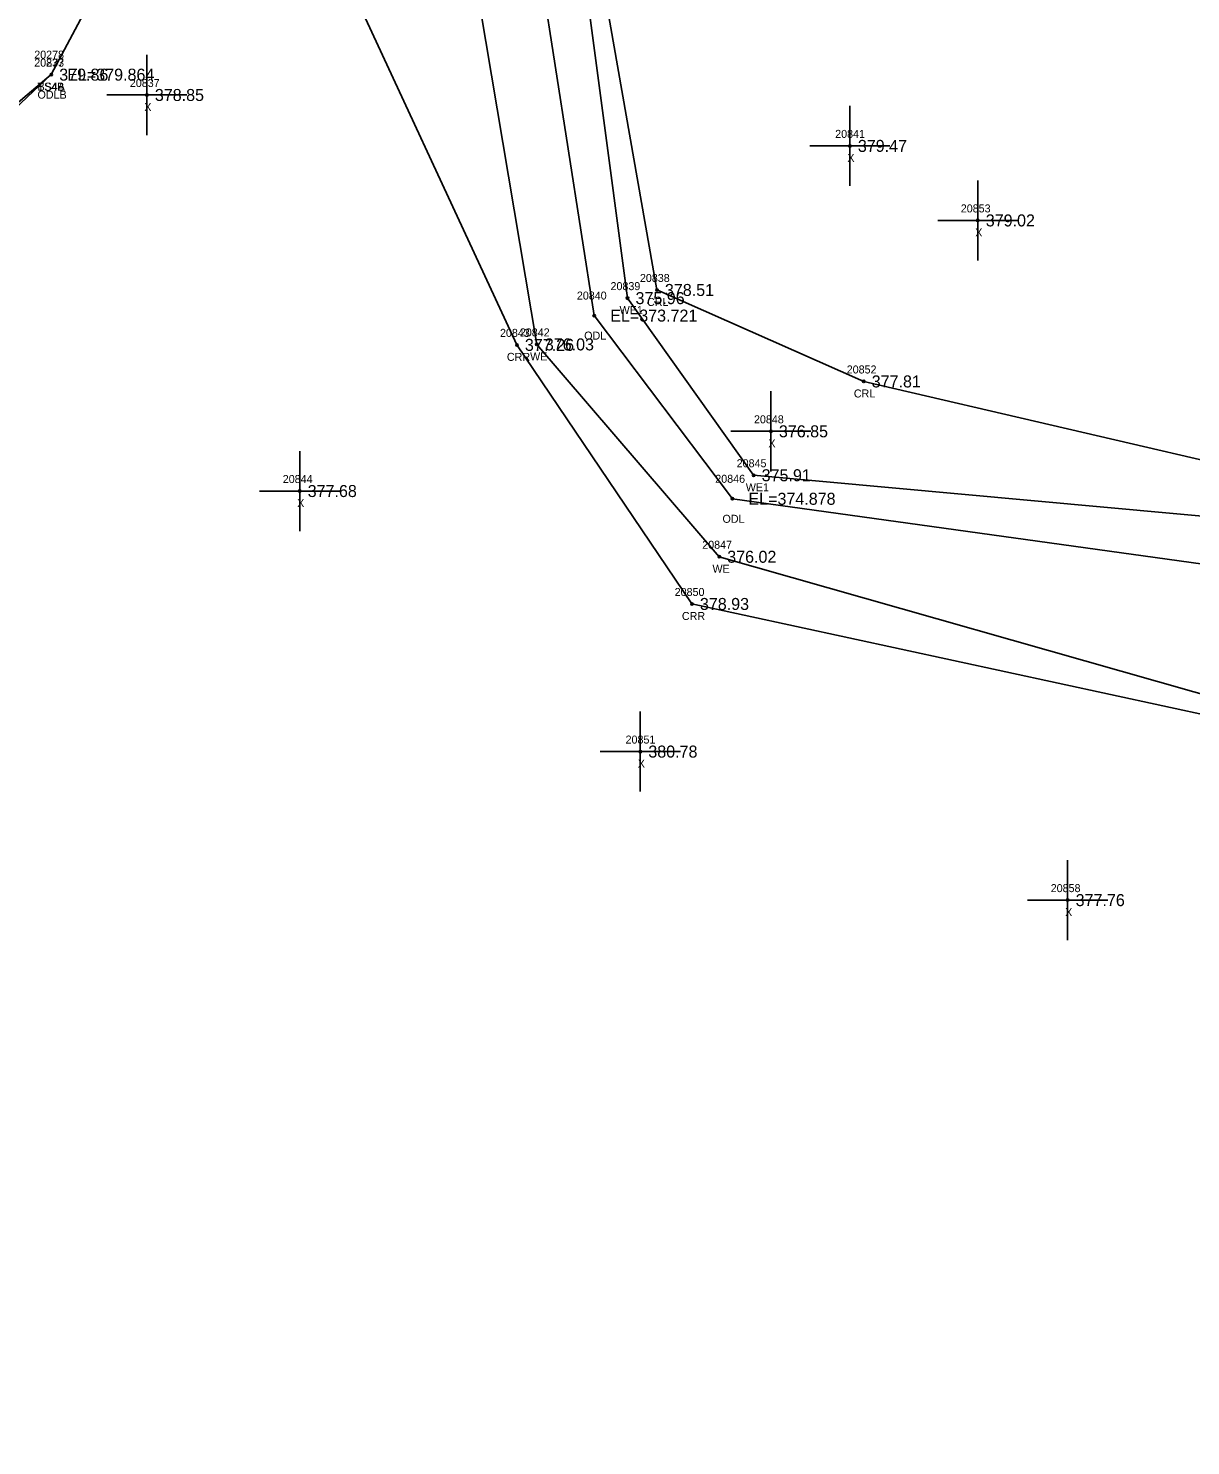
# Model space of a CAD drawing. Extents: x 2116373 to 2118139, y 979529 to 981026.
# Drawn here: x 2117341.9 to 2117487.1, y 979924.3 to 980101.3 of the extents above; entities that cross this region are included whole.
import ezdxf

# ---------------------------------------------------------------- set-up
doc = ezdxf.new("R2010")
doc.units = 0
for name, color, linetype in [('RD_DTM_BkLn2', 7, 'Continuous'), ('RD_DTM_BkLn_txCode', 7, 'Continuous'), ('RD_EX_H2O', 7, 'Continuous'), ('RD_EX_H2O_txCode', 7, 'Continuous'), ('RD_EX_Misc', 7, 'Continuous'), ('RD_EX_Misc_txCode', 7, 'Continuous'), ('RD_EX_TX_H2O_ELEV', 7, 'Continuous'), ('RD_EX_TX_Misc_ELEV', 7, 'Continuous'), ('RD_SMD_Locator', 7, 'Continuous')]:
    doc.layers.add(name, color=color, linetype=linetype)

msp = doc.modelspace()

# ---------------------------------------------------------------- linework, layer by layer
at = {"layer": 'RD_DTM_BkLn2'}
for points in [[(2117344.8, 980095.54), (2117358.39, 980121.14), (2117356.54, 980132.72)], [(2116934.42, 979772.82), (2116956.11, 979780.15), (2116996.15, 979805.42), (2117040.3, 979838.56), (2117080.53, 979868.79), (2117120.95, 979906.28), (2117189.36, 979974.74), (2117275.31, 980029.9), (2117344.8, 980095.54)]]:
    msp.add_lwpolyline(points, dxfattribs=at)
at = {"layer": 'RD_EX_H2O'}
for points in [[(2117055.27, 980533.4), (2117084.87, 980468.5), (2117113.12, 980396.82), (2117150.26, 980360.48), (2117172.14, 980330.53), (2117167.4, 980300.56), (2117152, 980282.05), (2117153.33, 980268.31), (2117164.01, 980260.72), (2117221.6, 980247.26), (2117265.25, 980211.02), (2117324.27, 980199.15), (2117347.37, 980175.31), (2117365.85, 980182.55), (2117389.45, 980162.29), (2117399.63, 980142.01), (2117411.26, 980120.88), (2117420.42, 980068.64), (2117446.24, 980057.21), (2117497.11, 980045.39), (2117594.71, 979999.33), (2117646.33, 979985.56), (2117750.91, 980032.44), (2117805.09, 980018.87)], [(2117320.83, 980195.76), (2117348.44, 980166.4), (2117344.42, 980159.47), (2117364.05, 980141.59), (2117409.75, 980120.17), (2117416.75, 980067.62), (2117432.5, 980045.49), (2117502.17, 980039.14), (2117583.98, 979987.26), (2117646.81, 979981.12), (2117705, 980001.51), (2117745.64, 980024.24), (2117805.06, 980014.37)], [(2117253.76, 980181.57), (2117309.73, 980180.01), (2117328.75, 980169.13), (2117302.89, 980172.19), (2117303.47, 980157.54), (2117331.87, 980146.51), (2117356.54, 980132.72), (2117379.52, 980112.38), (2117402.94, 980061.78), (2117424.79, 980029.41), (2117490.12, 980015.27), (2117551.05, 979984.61)], [(2117327.56, 980176.76), (2117343.89, 980156.23), (2117361.71, 980140.22), (2117404.48, 980117.53), (2117412.59, 980065.44), (2117429.85, 980042.55), (2117500.31, 980032.76), (2117583.13, 979982.49), (2117644.33, 979974.23), (2117711.62, 979990.62), (2117746.36, 980006.72), (2117805.28, 980007.14)], [(2117334.27, 980149.08), (2117359.88, 980134.92), (2117396.25, 980116.57), (2117405.43, 980061.84), (2117428.2, 980035.31), (2117491.98, 980017.16), (2117553.53, 979985.3), (2117578.12, 979975.29), (2117646.29, 979963.95), (2117711.26, 979981.91), (2117748.87, 979990.36), (2117810.8, 979988.9)], [(2116934.42, 979772.82), (2116952.72, 979786.01), (2116992.31, 979812.05), (2117036.21, 979845.2), (2117073.01, 979877), (2117113.79, 979913.05), (2117185.72, 979978.24), (2117270.2, 980032.33), (2117344.8, 980095.54)]]:
    msp.add_lwpolyline(points, dxfattribs=at)
at = {"layer": 'RD_EX_Misc'}
for p, q in [((2117356.74, 980088), (2117356.74, 980098)), ((2117351.74, 980093), (2117361.74, 980093)), ((2117444.51, 980081.64), (2117444.51, 980091.64)), ((2117439.51, 980086.64), (2117449.51, 980086.64)), ((2117460.48, 980072.33), (2117460.48, 980082.33)), ((2117455.48, 980077.33), (2117465.48, 980077.33)), ((2117434.65, 980045.98), (2117434.65, 980055.98)), ((2117429.65, 980050.98), (2117439.65, 980050.98)), ((2117375.82, 980038.52), (2117375.82, 980048.52)), ((2117370.82, 980043.52), (2117380.82, 980043.52)), ((2117418.35, 980005.97), (2117418.35, 980015.97)), ((2117413.35, 980010.97), (2117423.35, 980010.97)), ((2117471.7, 979987.41), (2117471.7, 979997.41)), ((2117466.7, 979992.41), (2117476.7, 979992.41))]:
    msp.add_line(p, q, dxfattribs=at)
at = {"layer": 'RD_SMD_Locator'}
for centre in [(2117344.8, 980095.54), (2117344.8, 980095.54), (2117344.8, 980095.54), (2117356.74, 980093), (2117444.51, 980086.64), (2117460.48, 980077.33), (2117420.42, 980068.64), (2117416.75, 980067.62), (2117412.59, 980065.44), (2117402.94, 980061.78), (2117405.43, 980061.84), (2117446.24, 980057.21), (2117434.65, 980050.98), (2117432.5, 980045.49), (2117375.82, 980043.52), (2117429.85, 980042.55), (2117428.2, 980035.31), (2117424.79, 980029.41), (2117418.35, 980010.97), (2117471.7, 979992.41)]:
    msp.add_circle(centre, 0.15, dxfattribs=at)

# ---------------------------------------------------------------- texts
at = {"layer": 'RD_DTM_BkLn_txCode'}
for s, p in [('20277', (2117342.68, 980096.54)), ('20833', (2117342.68, 980096.54)), ('TS4B', (2117343.09, 980093.54)), ('BS4A', (2117343.09, 980093.54))]:
    msp.add_text(s, height=1, dxfattribs=at).set_placement(p)
at = {"layer": 'RD_EX_H2O_txCode'}
for s, p in [('20278', (2117342.68, 980097.54)), ('ODLB', (2117343.09, 980092.54)), ('20838', (2117418.3, 980069.64)), ('20839', (2117414.63, 980068.62)), ('20840', (2117410.43, 980067.44)), ('CRL', (2117419.19, 980066.64)), ('WE1', (2117415.76, 980065.62)), ('20843', (2117400.83, 980062.78)), ('20842', (2117403.31, 980062.84)), ('ODL', (2117411.34, 980062.44)), ('CRR', (2117401.69, 980059.78)), ('WE', (2117404.59, 980059.84)), ('20852', (2117444.12, 980058.21)), ('CRL', (2117445.01, 980055.21)), ('20845', (2117430.38, 980046.49)), ('20846', (2117427.71, 980044.55)), ('WE1', (2117431.52, 980043.49)), ('ODL', (2117428.61, 980039.55)), ('20847', (2117426.08, 980036.31)), ('WE', (2117427.36, 980033.31)), ('20850', (2117422.64, 980030.41)), ('CRR', (2117423.54, 980027.41))]:
    msp.add_text(s, height=1, dxfattribs=at).set_placement(p)
at = {"layer": 'RD_EX_Misc_txCode'}
for s, p in [('20837', (2117354.62, 980094)), ('X', (2117356.42, 980091)), ('20841', (2117442.68, 980087.64)), ('X', (2117444.2, 980084.64)), ('20853', (2117458.36, 980078.33)), ('X', (2117460.16, 980075.33)), ('20848', (2117432.54, 980051.98)), ('X', (2117434.34, 980048.98)), ('20844', (2117373.71, 980044.52)), ('X', (2117375.51, 980041.52)), ('20851', (2117416.51, 980011.97)), ('X', (2117418.03, 980008.97)), ('20858', (2117469.59, 979993.41)), ('X', (2117471.39, 979990.41))]:
    msp.add_text(s, height=1, dxfattribs=at).set_placement(p)
at = {"layer": 'RD_EX_TX_H2O_ELEV'}
for s, p in [('EL=379.864', (2117346.8, 980094.79)), ('378.51', (2117421.42, 980067.89)), ('375.96', (2117417.75, 980066.87)), ('EL=373.721', (2117414.59, 980064.69)), ('377.26', (2117403.94, 980061.03)), ('376.03', (2117406.43, 980061.09)), ('377.81', (2117447.24, 980056.46)), ('375.91', (2117433.5, 980044.74)), ('EL=374.878', (2117431.85, 980041.8)), ('376.02', (2117429.2, 980034.56)), ('378.93', (2117425.79, 980028.66))]:
    msp.add_text(s, height=1.5, dxfattribs=at).set_placement(p)
at = {"layer": 'RD_EX_TX_Misc_ELEV'}
for s, p in [('379.86', (2117345.8, 980094.79)), ('379.86', (2117345.8, 980094.79)), ('378.85', (2117357.74, 980092.25)), ('379.47', (2117445.51, 980085.89)), ('379.02', (2117461.48, 980076.58)), ('376.85', (2117435.65, 980050.23)), ('377.68', (2117376.82, 980042.77)), ('380.78', (2117419.35, 980010.22)), ('377.76', (2117472.7, 979991.66))]:
    msp.add_text(s, height=1.5, dxfattribs=at).set_placement(p)

doc.saveas('drawing.dxf')
